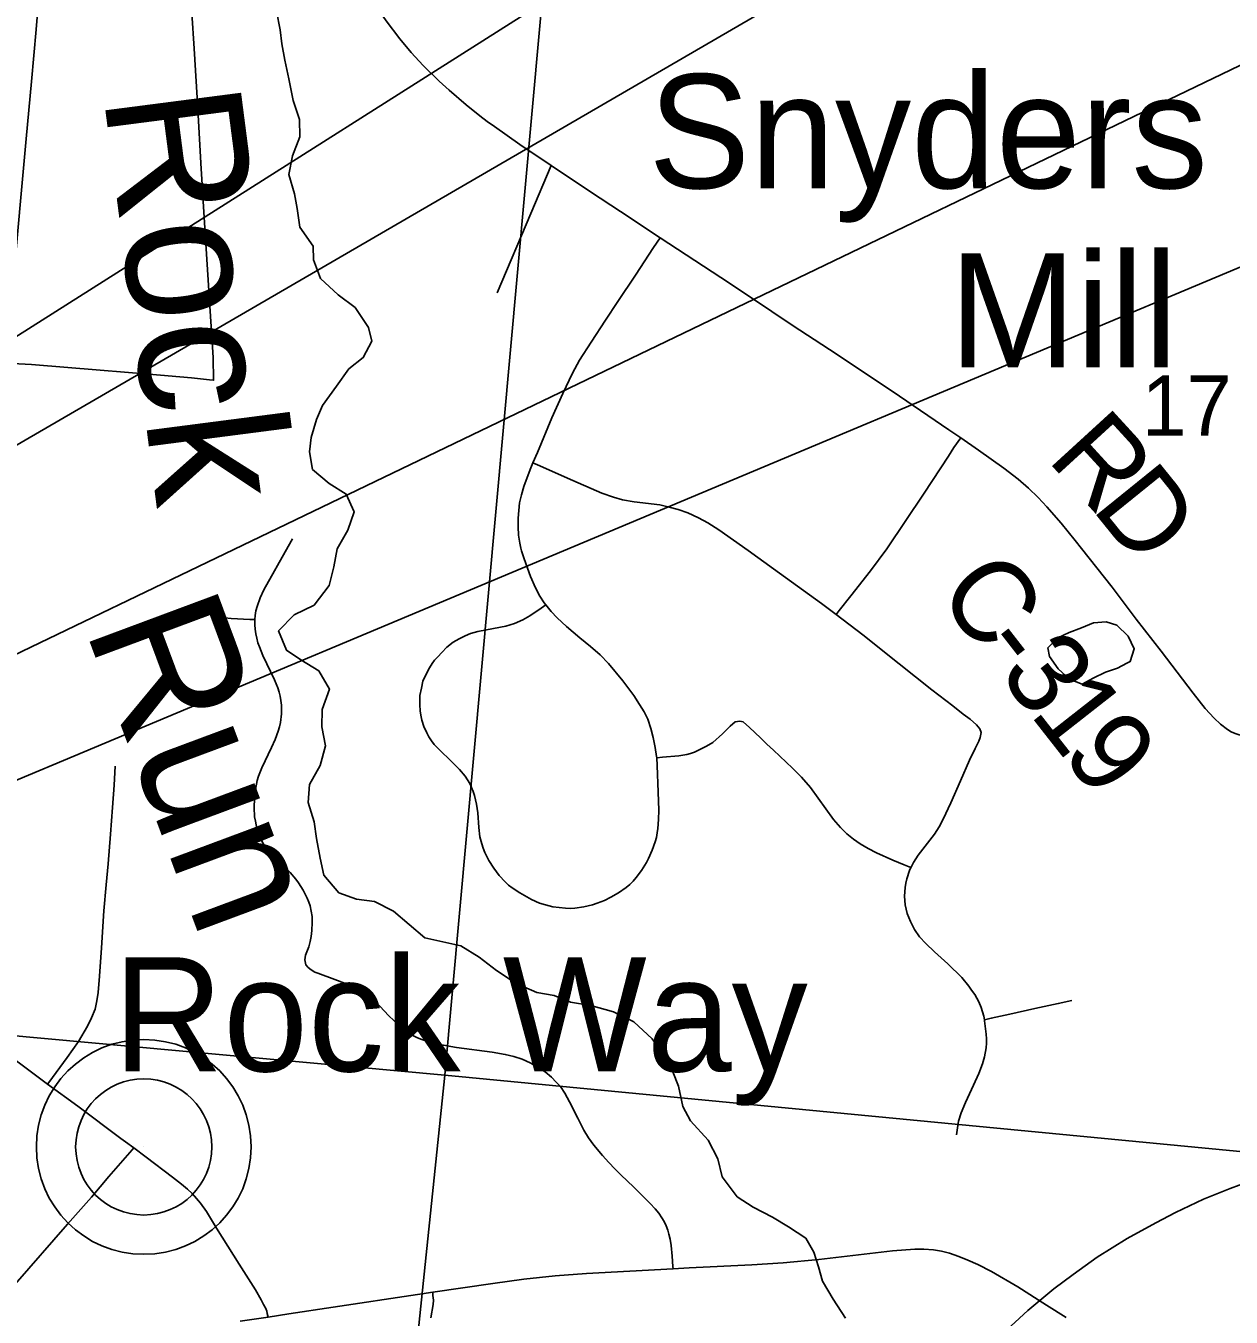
# Model space of a CAD drawing. Extents: x 0 to 34, y 0 to 22.
# Drawn here: x 5.887 to 6.722, y 18.097 to 18.991 of the extents above; entities that cross this region are included whole.
import ezdxf

# ---------------------------------------------------------------- set-up
doc = ezdxf.new("R2010")
doc.units = 0
for name, color, linetype in [('GM_X_County_Road', 7, 'Continuous'), ('GM_X_County_Road_Text', 7, 'Continuous'), ('GM_X_Minor_Lake', 7, 'Continuous'), ('GM_X_Minor_River', 7, 'Continuous'), ('GM_X_Minor_River_Text', 7, 'Continuous'), ('GM_X_Rail_Line', 7, 'Continuous'), ('GM_X_Section', 7, 'Continuous'), ('GM_X_Section_Text', 7, 'Continuous'), ('GM_X_Township_Road', 7, 'Continuous'), ('GM_X_Unincorporated', 7, 'Continuous'), ('GM_X_Unincorporated_Location', 7, 'Continuous'), ('GM_X_Unincorporated_Text', 7, 'Continuous'), ('GM_X_US_Route', 7, 'Continuous'), ('SH_Text', 7, 'Continuous')]:
    doc.layers.add(name, color=color, linetype=linetype)

msp = doc.modelspace()

# ---------------------------------------------------------------- linework, layer by layer
at = {"layer": 'GM_X_County_Road'}
msp.add_line((5.95581, 18.21796), (5.96152, 18.21372), dxfattribs=at)
for points in [[(6.25068, 18.89423), (6.22894, 18.90878), (6.21146, 18.92121), (6.2062, 18.92471), (6.2013, 18.92853), (6.19166, 18.93633), (6.17993, 18.94642), (6.17312, 18.95274), (6.16199, 18.96341), (6.15364, 18.97251), (6.14576, 18.98205), (6.13643, 18.99438), (6.12755, 19.00715)], [(6.32609, 18.84424), (6.32436, 18.84538), (6.30595, 18.85754), (6.28457, 18.87169), (6.25367, 18.89223), (6.25068, 18.89423)], [(6.53431, 18.70559), (6.52609, 18.71125), (6.49189, 18.73457), (6.46197, 18.75446), (6.44339, 18.76679), (6.41755, 18.78359), (6.3893, 18.80247), (6.36809, 18.81661), (6.32609, 18.84424)], [(6.61354, 18.63457), (6.60401, 18.64645), (6.59398, 18.65779), (6.58797, 18.6643), (6.5812, 18.67077), (6.57412, 18.6769), (6.56431, 18.68458), (6.54656, 18.69717), (6.53431, 18.70559)], [(6.84479, 18.51976), (6.83302, 18.51723), (6.78206, 18.50654), (6.76971, 18.50405), (6.7576, 18.50151), (6.74543, 18.49934), (6.73936, 18.49876), (6.73328, 18.49891), (6.73025, 18.49927), (6.72728, 18.49986), (6.72509, 18.50052), (6.72442, 18.50072), (6.72173, 18.50191), (6.71916, 18.50347), (6.71434, 18.50723), (6.70985, 18.51142), (6.70359, 18.51821), (6.69525, 18.52873), (6.67325, 18.55793), (6.65596, 18.58003), (6.63919, 18.60222), (6.61799, 18.62902), (6.61354, 18.63457)], [(5.84103, 18.2958), (5.84398, 18.2951), (5.84824, 18.2938), (5.85244, 18.29213), (5.85652, 18.29021), (5.86121, 18.28737), (5.88229, 18.27242), (5.89532, 18.26266), (5.9018, 18.25791)], [(5.9018, 18.25791), (5.9227, 18.24257), (5.95254, 18.22039), (5.95581, 18.21796)], [(5.96152, 18.21372), (5.97015, 18.20729), (5.98832, 18.19352), (5.99468, 18.18863), (5.9987, 18.18511), (6.00185, 18.18215), (6.005, 18.17881), (6.00778, 18.17541), (6.0118, 18.16966), (6.01891, 18.15824), (6.0346, 18.13333), (6.0459, 18.11535), (6.0498, 18.10843), (6.05149, 18.10532), (6.05288, 18.10253), (6.05357, 18.10065), (6.05394, 18.09916), (6.05457, 18.09664)]]:
    msp.add_lwpolyline(points, dxfattribs=at)
at = {"layer": 'GM_X_Minor_Lake'}
for points in [[(6.64937, 18.54941), (6.65178, 18.55065), (6.6545, 18.55936), (6.65041, 18.56812), (6.64252, 18.57577), (6.63498, 18.57811), (6.62627, 18.57741), (6.61792, 18.57406), (6.60957, 18.5707), (6.6016, 18.56696), (6.59474, 18.56018)], [(6.59474, 18.56018), (6.59582, 18.5541), (6.60181, 18.5457), (6.6097, 18.53843), (6.61837, 18.53495), (6.62597, 18.53907), (6.6347, 18.54319), (6.64305, 18.54616), (6.64937, 18.54941)]]:
    msp.add_lwpolyline(points, dxfattribs=at)
at = {"layer": 'GM_X_Minor_River'}
for points in [[(6.16323, 18.35927), (6.15236, 18.36852), (6.14146, 18.37777), (6.12825, 18.38438), (6.11573, 18.38605), (6.10363, 18.39037), (6.09315, 18.40266), (6.09064, 18.41447), (6.08816, 18.42818), (6.0864, 18.43961), (6.08239, 18.45296), (6.08331, 18.46549), (6.09069, 18.47871), (6.09429, 18.49235), (6.09179, 18.50531), (6.09195, 18.51747), (6.09706, 18.53147), (6.08962, 18.54411), (6.07719, 18.55186), (6.06739, 18.55843), (6.06187, 18.57181), (6.07265, 18.58308), (6.08641, 18.58976), (6.09683, 18.60333), (6.10004, 18.61622), (6.10247, 18.62873), (6.10985, 18.64157), (6.11419, 18.65445), (6.10865, 18.66668), (6.09697, 18.67404), (6.08532, 18.68368), (6.08319, 18.69588), (6.08446, 18.70575), (6.08804, 18.71825), (6.09234, 18.72808), (6.102, 18.74128), (6.11051, 18.75335), (6.12049, 18.76121), (6.12634, 18.77255), (6.12417, 18.78208), (6.11486, 18.79588), (6.10319, 18.80476), (6.0908, 18.81593), (6.08603, 18.82892), (6.08577, 18.83843), (6.07644, 18.85146), (6.0747, 18.86441), (6.07294, 18.8747), (6.06893, 18.88806), (6.07137, 18.90095), (6.07648, 18.9142), (6.07625, 18.92599), (6.07186, 18.93935), (6.06901, 18.95421), (6.06614, 18.96718), (6.064, 18.97861), (6.06298, 18.98813), (6.06049, 19.00108)], [(6.45456, 18.09592), (6.44596, 18.10888), (6.43849, 18.12146), (6.43592, 18.13134), (6.43259, 18.14161), (6.42699, 18.15114), (6.41495, 18.15919), (6.40403, 18.16572), (6.39046, 18.17265), (6.37955, 18.17995), (6.36906, 18.19368), (6.36613, 18.20623), (6.35942, 18.21918), (6.34705, 18.23255), (6.34183, 18.24246), (6.33891, 18.25652), (6.33482, 18.26641), (6.32961, 18.27708), (6.32063, 18.28929), (6.30786, 18.30115), (6.29391, 18.30808), (6.27806, 18.31237), (6.26408, 18.31475), (6.25277, 18.31939), (6.24068, 18.32138), (6.22635, 18.32755), (6.2128, 18.33676), (6.20077, 18.34596), (6.18797, 18.35364), (6.16323, 18.35927)]]:
    msp.add_lwpolyline(points, dxfattribs=at)
at = {"layer": 'GM_X_Rail_Line'}
msp.add_lwpolyline([(6.56339, 18.08496), (6.58086, 18.10125), (6.5989, 18.11621), (6.61221, 18.12618), (6.62889, 18.13798), (6.64972, 18.15096), (6.66952, 18.16197), (6.68319, 18.16902), (6.70259, 18.17816), (6.72105, 18.18571), (6.73964, 18.1926)], dxfattribs=at)
at = {"layer": 'GM_X_Section'}
for points in [[(5.2197, 19.35965), (6.2677, 19.26674), (6.17707, 18.26412), (5.13301, 18.35974)], [(6.2677, 19.26674), (7.26758, 19.17046), (7.17505, 18.16824), (6.17707, 18.26412)], [(5.13301, 18.35974), (6.17707, 18.26412), (6.07115, 17.24621), (5.04874, 17.32193)], [(6.17707, 18.26412), (7.17505, 18.16824), (7.08554, 17.16561), (6.07115, 17.24621)]]:
    msp.add_lwpolyline(points, close=True, dxfattribs=at)
at = {"layer": 'GM_X_Township_Road'}
for points in [[(5.89579, 19.01105), (5.89379, 18.98853), (5.89075, 18.9525), (5.88688, 18.91273), (5.88314, 18.86949), (5.87994, 18.83613), (5.87741, 18.8089), (5.87553, 18.7869), (5.8738, 18.765), (5.87318, 18.75743), (5.89056, 18.7563), (5.93818, 18.75256), (5.97202, 18.74968), (6.0014, 18.74707), (6.01393, 18.74573), (6.01676, 18.7455), (6.01643, 18.76132), (6.01355, 18.80765), (6.01056, 18.85462), (6.008, 18.89594), (6.00591, 18.93343), (6.0033, 18.97516), (6.00181, 18.99971)], [(6.25068, 18.89423), (6.23651, 18.8609), (6.21317, 18.80604)], [(6.23801, 18.68821), (6.24106, 18.69539), (6.2512, 18.71938), (6.25876, 18.73628), (6.26536, 18.75028), (6.27019, 18.75945), (6.2784, 18.77184), (6.28838, 18.78714), (6.29675, 18.80001), (6.30898, 18.81836), (6.32153, 18.83736), (6.32609, 18.84424)], [(6.44795, 18.58319), (6.45025, 18.58611), (6.45815, 18.59609), (6.47183, 18.61348), (6.48326, 18.62877), (6.50902, 18.66726), (6.52593, 18.69301), (6.52963, 18.69897), (6.53431, 18.70559)], [(6.22973, 18.62908), (6.22898, 18.63262), (6.22802, 18.63826), (6.2277, 18.64405), (6.22786, 18.65001), (6.22818, 18.65532), (6.22882, 18.66047), (6.23011, 18.6661), (6.23172, 18.6719), (6.23607, 18.68365), (6.23801, 18.68821)], [(6.23801, 18.68821), (6.24282, 18.6861), (6.26189, 18.67771), (6.28573, 18.66735), (6.29378, 18.66439), (6.30003, 18.66275), (6.30825, 18.66127), (6.32601, 18.65913), (6.33242, 18.65749), (6.3385, 18.65601), (6.34524, 18.6537), (6.35281, 18.65025), (6.35905, 18.6468), (6.36678, 18.64187), (6.387, 18.62757), (6.40459, 18.6149), (6.4378, 18.5909), (6.44795, 18.58319)], [(6.04544, 18.57971), (6.04566, 18.58253), (6.04617, 18.58567), (6.04692, 18.58876), (6.04905, 18.59472), (6.05168, 18.60043), (6.06849, 18.63022), (6.07155, 18.6356)], [(6.24685, 18.58999), (6.24572, 18.59142), (6.24283, 18.59592), (6.23977, 18.60172), (6.23637, 18.60949), (6.23188, 18.62168), (6.23011, 18.62731), (6.22973, 18.62908)], [(6.24685, 18.58999), (6.24363, 18.58771), (6.23591, 18.58225), (6.23092, 18.57951), (6.22528, 18.57709), (6.21933, 18.57516), (6.2108, 18.57355), (6.19985, 18.57146), (6.1947, 18.57001), (6.191, 18.5684), (6.18697, 18.56647), (6.18279, 18.56406), (6.17844, 18.56052), (6.17491, 18.55697), (6.17219, 18.554), (6.16992, 18.55166), (6.16815, 18.54925), (6.16638, 18.54635), (6.16396, 18.54201), (6.16186, 18.53702), (6.16074, 18.53219), (6.15978, 18.52704), (6.15962, 18.5206), (6.15994, 18.51657), (6.16042, 18.51352), (6.16106, 18.50997), (6.16235, 18.50563), (6.16451, 18.50126), (6.16597, 18.49843), (6.16772, 18.49577), (6.16971, 18.4933), (6.17404, 18.48879), (6.18074, 18.48239), (6.18715, 18.47581), (6.19108, 18.47121), (6.19278, 18.46876), (6.19426, 18.46617), (6.19554, 18.46345), (6.19664, 18.46064), (6.19759, 18.45778), (6.19896, 18.45186), (6.19989, 18.4458), (6.2005, 18.43561), (6.2013, 18.42934), (6.20259, 18.42431), (6.20355, 18.42129), (6.20472, 18.41838), (6.20749, 18.4128), (6.21082, 18.40749), (6.21464, 18.40253), (6.21889, 18.39797), (6.2212, 18.39582), (6.22364, 18.39383), (6.22885, 18.39034), (6.23698, 18.38572), (6.24267, 18.38331), (6.24669, 18.38202), (6.25185, 18.38077), (6.26056, 18.37971)], [(6.32374, 18.48405), (6.32368, 18.48497), (6.32275, 18.4912), (6.32137, 18.49806), (6.31976, 18.50418), (6.31751, 18.51062), (6.31509, 18.51577), (6.31188, 18.52092), (6.30801, 18.52704), (6.30029, 18.53718), (6.29047, 18.54925), (6.28467, 18.55537), (6.27786, 18.56118), (6.27061, 18.56712), (6.26118, 18.57484), (6.25473, 18.58095), (6.25055, 18.5853), (6.24685, 18.58999)], [(6.02018, 18.58129), (6.02903, 18.58038), (6.042, 18.57985), (6.04544, 18.57971)], [(6.33507, 18.13005), (6.33497, 18.13168), (6.33453, 18.13882), (6.33381, 18.14611), (6.33316, 18.15065), (6.33223, 18.15411), (6.33143, 18.15678), (6.33028, 18.15974), (6.32898, 18.16269), (6.3273, 18.16542), (6.32527, 18.16853), (6.32271, 18.17164), (6.3192, 18.17537), (6.31503, 18.17944), (6.31123, 18.18323), (6.30766, 18.18683), (6.29919, 18.19487), (6.29483, 18.1992), (6.29064, 18.20356), (6.2862, 18.20842), (6.28019, 18.21562), (6.27656, 18.22072), (6.27333, 18.2261), (6.26913, 18.23446), (6.26343, 18.24563), (6.26003, 18.25176), (6.25708, 18.25623), (6.25419, 18.2594), (6.25081, 18.26287), (6.24658, 18.26638), (6.24144, 18.26968), (6.23605, 18.27264), (6.2305, 18.27516), (6.22473, 18.27708), (6.21878, 18.27849), (6.20967, 18.28001), (6.18513, 18.28327), (6.17597, 18.28489), (6.16988, 18.28624), (6.16385, 18.28795), (6.16094, 18.28893), (6.15807, 18.29007), (6.15526, 18.29141), (6.15251, 18.29297), (6.14988, 18.29474), (6.14501, 18.29874), (6.13824, 18.30518), (6.13192, 18.31202), (6.12763, 18.31637), (6.12535, 18.31837), (6.12294, 18.32021), (6.12041, 18.32189), (6.11777, 18.32337), (6.11222, 18.32596), (6.10072, 18.33047), (6.08902, 18.33469), (6.08696, 18.33557), (6.08443, 18.33707), (6.08227, 18.33881), (6.08068, 18.34061), (6.07997, 18.34397), (6.08056, 18.34726), (6.0827, 18.35301), (6.08371, 18.35683), (6.08436, 18.36022), (6.08493, 18.36441), (6.08515, 18.36996), (6.08501, 18.374), (6.0845, 18.37775), (6.08363, 18.38138), (6.08275, 18.38398), (6.08153, 18.38684), (6.07879, 18.39221), (6.07726, 18.39482), (6.07559, 18.39736), (6.07379, 18.39982), (6.06983, 18.40447), (6.0655, 18.40873), (6.06087, 18.41288), (6.0586, 18.41505), (6.05439, 18.41981), (6.05252, 18.42239), (6.05082, 18.4251), (6.04933, 18.42792), (6.04809, 18.43085), (6.0471, 18.43387), (6.04572, 18.44004), (6.04524, 18.44315), (6.04484, 18.44946), (6.04505, 18.45575), (6.04575, 18.46199), (6.04698, 18.46818), (6.04787, 18.47121), (6.05015, 18.47706), (6.05683, 18.49113), (6.05943, 18.49673), (6.06159, 18.50245), (6.06241, 18.50538), (6.06304, 18.50836), (6.06373, 18.51442), (6.06373, 18.52054), (6.06345, 18.52357), (6.06298, 18.52658), (6.06229, 18.52953), (6.06136, 18.53242), (6.05898, 18.53807), (6.05096, 18.55492), (6.04855, 18.56072), (6.04753, 18.56372), (6.04673, 18.56678), (6.04612, 18.56988), (6.04568, 18.57301), (6.04544, 18.57617), (6.04543, 18.57754), (6.04544, 18.57971)], [(6.44795, 18.58319), (6.46657, 18.56904), (6.49173, 18.54915), (6.51441, 18.53106), (6.52878, 18.51999), (6.53612, 18.51429), (6.54088, 18.51068), (6.54532, 18.50689), (6.54762, 18.5041), (6.54844, 18.50147), (6.54779, 18.49801), (6.5468, 18.49538), (6.54434, 18.49045), (6.54039, 18.48223), (6.53414, 18.46809), (6.52747, 18.45282), (6.5222, 18.44153), (6.51933, 18.43613), (6.51621, 18.43118), (6.5049, 18.41661), (6.5016, 18.41146), (6.50019, 18.40877), (6.49985, 18.40797)], [(6.32374, 18.48405), (6.32781, 18.48439), (6.33907, 18.4853), (6.34462, 18.48629), (6.34718, 18.487), (6.34987, 18.48797), (6.3527, 18.4892), (6.35831, 18.49207), (6.36257, 18.49468), (6.36933, 18.50064), (6.37465, 18.50579), (6.37819, 18.50885), (6.38141, 18.50933), (6.38366, 18.50885), (6.38801, 18.50498), (6.39567, 18.49773), (6.40012, 18.49345), (6.40456, 18.48926), (6.40901, 18.48512), (6.41786, 18.47674), (6.42406, 18.47054), (6.43018, 18.46346), (6.44627, 18.44125), (6.4511, 18.43561), (6.45544, 18.43127), (6.45995, 18.42757), (6.46462, 18.42435), (6.47025, 18.42113), (6.47605, 18.41824), (6.48731, 18.41308), (6.4952, 18.40987), (6.49985, 18.40797)], [(6.26056, 18.37971), (6.26378, 18.37958), (6.26694, 18.37977), (6.27318, 18.38064), (6.27937, 18.38211), (6.28262, 18.38317), (6.2875, 18.38509), (6.29189, 18.38739), (6.29739, 18.39039), (6.30269, 18.39425), (6.30513, 18.39631), (6.30737, 18.39859), (6.30943, 18.40099), (6.31319, 18.40601), (6.31657, 18.41134), (6.31802, 18.41415), (6.32056, 18.41988), (6.32271, 18.42577), (6.32354, 18.42883), (6.32416, 18.43193), (6.3246, 18.43506), (6.32507, 18.44133), (6.32515, 18.4476), (6.32469, 18.46007), (6.3241, 18.47871), (6.32374, 18.48405)], [(5.9018, 18.25791), (5.90272, 18.25916), (5.91542, 18.2764), (5.92317, 18.28736), (5.92945, 18.29805), (5.93226, 18.30393), (5.93467, 18.30981), (5.936, 18.31569), (5.9368, 18.32144), (5.93774, 18.33267), (5.93921, 18.35244), (5.94081, 18.37797), (5.94242, 18.39601), (5.94389, 18.41044), (5.94535, 18.43116), (5.9467, 18.4496), (5.94803, 18.46497), (5.94857, 18.4782)], [(6.49985, 18.40797), (6.49897, 18.40598), (6.49706, 18.40018), (6.49637, 18.3972), (6.49587, 18.39419), (6.49556, 18.39116), (6.49543, 18.38812), (6.49552, 18.38509), (6.49586, 18.38208), (6.49646, 18.37911), (6.49727, 18.3762), (6.49947, 18.37051), (6.50229, 18.36508), (6.50586, 18.36008), (6.51014, 18.35531), (6.51622, 18.34956), (6.52543, 18.34117), (6.53513, 18.3318), (6.53989, 18.32588), (6.54187, 18.32309), (6.54401, 18.32013), (6.54696, 18.31487), (6.5484, 18.31102), (6.54949, 18.30802), (6.55032, 18.30495), (6.55079, 18.30249)], [(6.55079, 18.30249), (6.55551, 18.30352), (6.56834, 18.30632), (6.58576, 18.31027), (6.60188, 18.31371), (6.61141, 18.31585)], [(6.55079, 18.30249), (6.55092, 18.30182), (6.55198, 18.29251), (6.55221, 18.28941), (6.55223, 18.28625), (6.55198, 18.28311), (6.55087, 18.27687), (6.54943, 18.27196), (6.54696, 18.26538), (6.54318, 18.25716), (6.53759, 18.24516), (6.53464, 18.23809), (6.53283, 18.23217), (6.532, 18.22757), (6.5313, 18.22276)], [(5.87946, 18.1194), (5.91568, 18.16088), (5.93212, 18.17975), (5.94434, 18.19399), (5.95554, 18.207), (5.9604, 18.21247), (5.96152, 18.21372)], [(6.16738, 18.09597), (6.16879, 18.10524), (6.16904, 18.10841), (6.16876, 18.11159), (6.16858, 18.11374)]]:
    msp.add_lwpolyline(points, dxfattribs=at)
at = {"layer": 'GM_X_Unincorporated'}
for radius in [0.0744, 0.04716]:
    msp.add_circle((5.96842, 18.21445), radius, dxfattribs=at)
at = {"layer": 'GM_X_Unincorporated_Location'}
msp.add_line((5.96842, 18.21445), (5.96842, 18.21445), dxfattribs=at)
at = {"layer": 'GM_X_US_Route'}
msp.add_lwpolyline([(6.0352, 18.09383), (6.05457, 18.09664), (6.06898, 18.09873), (6.09963, 18.10334), (6.15794, 18.11217), (6.16858, 18.11374), (6.21015, 18.11986), (6.23171, 18.12275), (6.25334, 18.12507), (6.27502, 18.12674), (6.33507, 18.13005), (6.3463, 18.13067), (6.38968, 18.13284), (6.41134, 18.13424), (6.43603, 18.13652), (6.48715, 18.14237), (6.50259, 18.14372), (6.50884, 18.14372), (6.51546, 18.14311), (6.52098, 18.14213), (6.52661, 18.14078), (6.53311, 18.13858), (6.53937, 18.136), (6.54623, 18.13293), (6.55567, 18.12815), (6.57393, 18.11749), (6.59379, 18.10486), (6.6074, 18.0964)], dxfattribs=at)
at = {"layer": 'SH_Text'}
for points in [[(9.2218, 20.89411), (4.45803, 17.87452), (9.2218, 20.64169)], [(9.24529, 20.17502), (4.46592, 17.8756), (9.24529, 19.87959)]]:
    msp.add_lwpolyline(points, close=True, dxfattribs=at)

# ---------------------------------------------------------------- texts
at = {"layer": 'GM_X_County_Road_Text'}
for s, rotation, p in [('R', 312.44907, (6.59338, 18.69064)), ('D', 308.95338, (6.62428, 18.6569)), ('C', 307.84179, (6.51683, 18.59764)), ('-', 307.86995, (6.54547, 18.56076)), ('3', 307.90949, (6.55982, 18.54231)), ('1', 308.09641, (6.58145, 18.51454)), ('9', 308.66537, (6.60343, 18.48651))]:
    msp.add_text(s, height=0.05682, rotation=rotation, dxfattribs=at).set_placement(p)
at = {"layer": 'GM_X_Minor_River_Text'}
for s, height, rotation, p in [('Rock', 0.094801, 277.37265, (5.9405, 18.94279)), ('Run', 0.09476, 290.43216, (5.92729, 18.57411))]:
    msp.add_text(s, height=height, rotation=rotation, dxfattribs=at).set_placement(p)
at = {"layer": 'GM_X_Section_Text'}
msp.add_text('17', height=0.041856, rotation=0.00001, dxfattribs=at).set_placement((6.6597, 18.70703))
at = {"layer": 'GM_X_Unincorporated_Text'}
for s, p in [('Snyders', (6.31804, 18.87849)), ('Mill', (6.52637, 18.75432)), ('Rock Way', (5.9472, 18.26682))]:
    msp.add_text(s, height=0.078977, rotation=0.00001, dxfattribs=at).set_placement(p)

doc.saveas('drawing.dxf')
